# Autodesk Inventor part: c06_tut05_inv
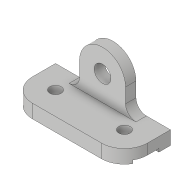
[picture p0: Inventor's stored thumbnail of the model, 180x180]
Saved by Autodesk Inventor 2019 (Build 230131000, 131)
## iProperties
Created: 2015-03
Part Number: c06_tut05_inv
Material: Generic
Document SubType Name: Modeling
Designer: Sandeep
Density: 1 g/cm^3
Appearance: Default
Author: Sandeep
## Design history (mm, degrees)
sketch "Sketch1"
  geometry: L1 (-11, 0)-(11, 0); L2 (11, 0)-(11, -3); L3 (11, -3)-(22, -3); L4 (22, -3)-(22, 10); L5 (22, 10)-(-22, 10); L6 (-22, 10)-(-22, -3); L7 (-22, -3)-(-11, -3); L8 (-11, -3)-(-11, 0); L9 (0, 13.216)-(0, -4.005); 2 further points
  constraints: 18 end point, 6 perpendicular, 4 point on line, 2 midpoint, 1 horizontal, 1 vertical, 1 other
  dimensions: "d0" = 22 distance of L1.start L1.end; "d1" = 44 distance of L4.end L5.end; "d2" = 3 distance between parallel lines of L1 L3; "d3" = 13 distance between parallel lines of L5 L3
extrude "Extrusion1" new body sketch "Sketch1" stored distance "d4" = 110; taper "d5" = 0 deg
fillet "Fillet1" dims "d6" = 22
mirror "Mirror1"
sketch "Sketch2"
  geometry: L1 (22, 0)-(88, 0) reference; L2 (77, 0)-(77, -24); L3 (33, -24)-(33, 0); L4 (77, 0)-(33, 0); L5 (0, 13)-(110, 13) reference; L6 (0, 0)-(0, 13) reference; C1 r 8 at (55, -24); A1 r 22 centre (55, -24) between (33, -24) and (77, -24); 1 further point
  constraints: 6 end point, 2 centre point, 2 point on circle, 2 point on line, 2 tangent, 1 coincident, 1 collinear, 1 parallel, 1 vertical
  dimensions: "d7" = 22 radius of A1; "d8" = 37 distance from line of L5 A1.centre; "d9" = 55 distance from line of L6 A1.centre; "d23" = 16 diameter of C1
extrude "Extrusion2" join sketch "Sketch2" distance "d11" = 10; taper "d12" = 0 deg
fillet "Fillet2" dims "d13" = 10
mirror "Mirror2"
hole "Hole1" diameter "d16" = 11; stored, may be unused: countersink angle "d20" = 90 deg, drill point angle "d22" = 118 deg; dims "d14" = 10, "d15" = 10, "d17" = 6, "d18" = 4, "d19" = 2, "d21" = 8
mirror "Mirror3"
body "Solid1"
